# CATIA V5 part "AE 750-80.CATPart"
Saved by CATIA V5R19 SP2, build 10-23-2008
Part number: AE 750-80
Bounding box of the stored display mesh (mm): x -24.865 to 24.865, y -24.997 to 24.997, z 0 to 210
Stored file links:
  C:\Users\Bora\Desktop\3D Katı model\AE serisi\AE 750\AE 750-80.CATPart
  C:\Program Files\Dassault Systemes\B19\intel_a\reffiles\standard\MetricThickPitch.txt
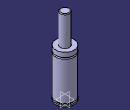
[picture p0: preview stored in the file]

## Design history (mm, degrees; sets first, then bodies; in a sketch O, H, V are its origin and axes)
Body1 (main body)
  Sketch1 on yz-plane, origin (0, 0, 0), H (0, 1, 0), V (0, 0, 1)
    point P1 (25, 112.5)
    point P8 (25, 116.5)
    point P9 (12.5, 208)
    point P11 (12.5, 208)
    point P13 (25, 116.5)
    point P14 (25, 112.5)
    line L1 (25, 112.5) -> (25, 8)
    line L2 (25, 4) -> (25, 0)
    line L3 (21.5, 8) -> (21.5, 4)
    line L4 (25, 129) -> (25, 116.5)
    line L5 (12.5, 208) -> (12.5, 129)
    arc A1 centre (10.5, 208) radius 2 from (12.5, 208) to (10.5, 210) ccw
    arc A2 centre (25, 114.5) radius 2 from (25, 116.5) to (25, 112.5) ccw
    line L6 (10.5, 210) -> (0, 210)
    point P15 (0, 210)
    line L7 (12.5, 129) -> (25, 129)
    line L8 (0, 0) -> (25, 0)
    line L9 (21.5, 8) -> (25, 8)
    line L10 (21.5, 4) -> (25, 4)
    coincidence: P15 V, P1 P14, P8 P13, P9 P11
    tangency: L6 A1
    horizontal: L7 H, L8 H, L9 H, L10 H
  Shaft1: profile Sketch1, axis Sketch1.V, angle 360
  Sketch2 on face of Shaft1 from Sketch1.L8, origin (0, 0, 0), H (1, 0, 0), V (0, -1, 0)
    point P1 (10, 0)
    distance P1 V = 10
  Hole1: placed by Sketch2, at (10, 0, 0) direction (0, 0, 1), diameter 6.647, depth 13, threaded "M8", thread diameter 8, thread depth 13, pitch 1.25
  CircPattern1: of Hole1, instances 2, angular step 180, axis from xy-plane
